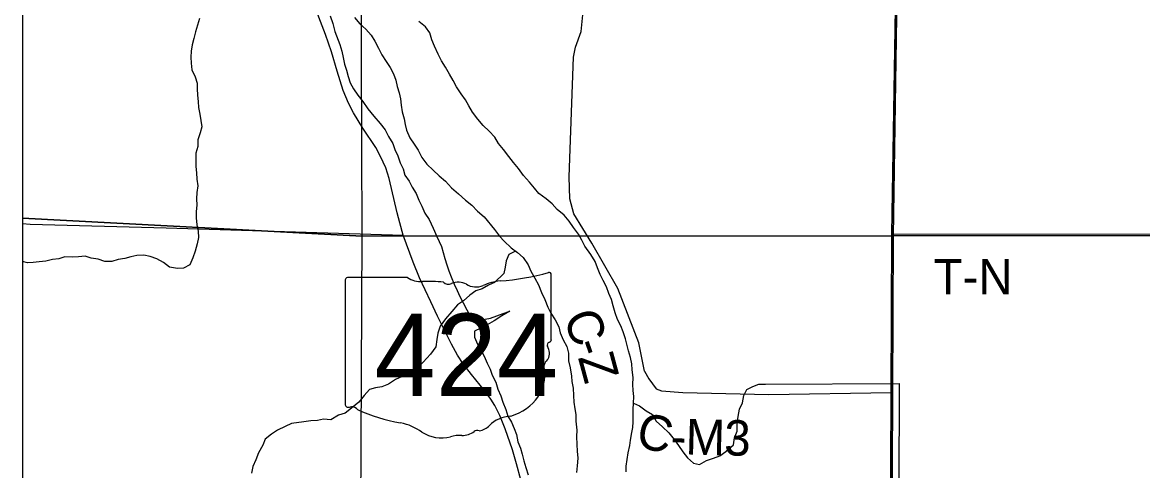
# Model space of a CAD drawing. Extents: x -6.2 to 37.4, y 0.2 to 22.2.
# Drawn here: x 1.681 to 2.577, y 15.692 to 16.05 of the extents above; entities that cross this region are included whole.
import ezdxf

# ---------------------------------------------------------------- set-up
doc = ezdxf.new("R2010")
doc.units = 0
for name, color, linetype in [('GM_X_County_Road', 7, 'Continuous'), ('GM_X_County_Road_Text', 7, 'Continuous'), ('GM_X_Major_River', 7, 'Continuous'), ('GM_X_Minor_River', 7, 'Continuous'), ('GM_X_Rail_Line', 7, 'Continuous'), ('GM_X_Section', 7, 'Continuous'), ('GM_X_State_Location', 7, 'Continuous'), ('GM_X_State_Shield', 7, 'Continuous'), ('GM_X_Township_Road', 7, 'Continuous'), ('GM_X_Township_Road_Text', 7, 'Continuous'), ('GM_X_US_Shield', 7, 'Continuous'), ('SH_Cut_Line', 7, 'Continuous'), ('SH_Data', 7, 'Continuous')]:
    doc.layers.add(name, color=color, linetype=linetype)

msp = doc.modelspace()

# ---------------------------------------------------------------- linework, layer by layer
at = {"layer": 'GM_X_County_Road'}
for points in [[(2.17886, 15.77135), (2.17423, 15.79416), (2.15735, 15.83754), (2.13664, 15.8739), (2.12213, 15.89714), (2.11897, 15.90931), (2.11849, 15.92697), (2.12203, 16.02247), (2.12359, 16.03044), (2.12822, 16.04296), (2.13103, 16.07276), (2.1317, 16.09117), (2.13443, 16.10446), (2.14488, 16.13992), (2.16169, 16.19805), (2.20351, 16.34266), (2.20755, 16.35308), (2.21368, 16.36217), (2.32755, 16.53511), (2.34687, 16.56576), (2.35511, 16.57606), (2.36464, 16.58624), (2.37224, 16.59399), (2.38743, 16.6095)], [(2.3744, 15.3797), (2.37573, 15.63221), (2.37619, 15.75431), (2.37666, 15.88116), (2.38391, 16.32379), (2.3895, 16.61161)], [(2.07985, 15.68454), (2.07645, 15.69747), (2.07312, 15.70847), (2.06716, 15.7254), (2.06302, 15.73606), (2.05889, 15.74394), (2.05591, 15.74906), (2.05083, 15.75596), (2.04021, 15.76886), (2.03362, 15.77727), (2.02899, 15.78432), (2.0243, 15.79294), (2.01897, 15.80363), (2.01322, 15.81555), (2.00779, 15.8268), (1.99868, 15.84597), (1.99355, 15.85851), (1.98575, 15.88021), (1.9829, 15.89009), (1.98084, 15.89805), (1.97446, 15.92542), (1.97165, 15.93408), (1.96762, 15.94322), (1.96366, 15.95037), (1.95343, 15.9658), (1.94589, 15.97796), (1.94176, 15.98563), (1.93769, 15.99594), (1.93282, 16.01129), (1.92833, 16.02671), (1.92346, 16.04076), (1.91333, 16.06715)], [(2.17886, 15.77135), (2.18225, 15.76545), (2.1881, 15.75745), (2.19227, 15.75572), (2.20955, 15.75431), (2.27832, 15.75267), (2.37619, 15.75431)]]:
    msp.add_lwpolyline(points, dxfattribs=at)
at = {"layer": 'GM_X_Major_River'}
for points in [[(1.94657, 16.05425), (1.95084, 16.04906), (1.9557, 16.045), (1.96004, 16.04005), (1.96293, 16.0354), (1.96587, 16.02985), (1.96866, 16.0245), (1.97194, 16.01913), (1.97527, 16.01414), (1.97799, 16.00925), (1.97965, 16.00402), (1.98089, 15.99906), (1.98251, 15.9941), (1.98356, 15.98915), (1.98405, 15.98421), (1.9849, 15.97869), (1.98633, 15.97335), (1.9872, 15.9686), (1.98837, 15.96406), (1.991, 15.9581), (1.99432, 15.95292), (1.99765, 15.94813), (2.00058, 15.9422), (2.00448, 15.93701), (2.00951, 15.93219), (2.01455, 15.92756), (2.01941, 15.92331), (2.02443, 15.91792), (2.02985, 15.91328), (2.03545, 15.90826), (2.04069, 15.9042), (2.04516, 15.89939), (2.05058, 15.89475), (2.05875, 15.88475), (2.06264, 15.87938), (2.06636, 15.87527), (2.07215, 15.87013), (2.07706, 15.86629), (2.08166, 15.86223), (2.08556, 15.85645), (2.08794, 15.85128), (2.09107, 15.84592), (2.09382, 15.84038), (2.09637, 15.83445), (2.09912, 15.82872), (2.10148, 15.82261), (2.10386, 15.81783), (2.10729, 15.81259), (2.11012, 15.80691), (2.11136, 15.80215), (2.11373, 15.79661), (2.11668, 15.79125), (2.11791, 15.78592), (2.118, 15.77984), (2.11924, 15.77416), (2.12042, 15.76754), (2.12075, 15.76328), (2.1216, 15.75777), (2.12188, 15.75207), (2.12217, 15.74656), (2.12295, 15.7414), (2.12381, 15.73669), (2.12392, 15.73146), (2.12463, 15.72431), (2.12436, 15.71919), (2.12463, 15.71274), (2.12491, 15.70742), (2.12539, 15.7019), (2.12491, 15.69584), (2.12443, 15.69034)], [(2.02276, 16.00906), (2.01963, 16.01461), (2.0162, 16.01964), (2.01375, 16.02495), (2.01063, 16.03126), (2.00863, 16.03642), (2.00702, 16.04194), (2.0035, 16.04674), (1.99808, 16.051)], [(2.16406, 15.69088), (2.16414, 15.69562), (2.1648, 15.70074), (2.16584, 15.70604), (2.16696, 15.71208), (2.16749, 15.71636), (2.16856, 15.72245), (2.16941, 15.72652), (2.16967, 15.73103), (2.16976, 15.73597), (2.16965, 15.74091), (2.16993, 15.74584), (2.17021, 15.75115), (2.16972, 15.75609), (2.16942, 15.76084), (2.16971, 15.76634), (2.16887, 15.77262), (2.16876, 15.77736), (2.1677, 15.78231), (2.16609, 15.78765), (2.1636, 15.79718), (2.16161, 15.80291), (2.1598, 15.80768), (2.15723, 15.81284), (2.15542, 15.81799), (2.15381, 15.82371), (2.15238, 15.82867), (2.15038, 15.83364), (2.14839, 15.83898), (2.14582, 15.84395), (2.14343, 15.84874), (2.14125, 15.85408), (2.13944, 15.85901), (2.13594, 15.86479), (2.13104, 15.87146), (2.12874, 15.8761), (2.12598, 15.88108), (2.12208, 15.88626), (2.11857, 15.89144), (2.11461, 15.89631), (2.10894, 15.9008), (2.10497, 15.90512), (2.10011, 15.90937), (2.09429, 15.91361), (2.09078, 15.91787), (2.08688, 15.92267), (2.08185, 15.92787), (2.07796, 15.93344), (2.07388, 15.93843), (2.07017, 15.94323), (2.0659, 15.94861), (2.06181, 15.95361), (2.05887, 15.95859), (2.05459, 15.9634), (2.04974, 15.96784), (2.04527, 15.97303), (2.04101, 15.9786), (2.03825, 15.98358), (2.03549, 15.98836), (2.03216, 15.99316), (2.02828, 15.99891), (2.02552, 16.00389), (2.02276, 16.00906)]]:
    msp.add_lwpolyline(points, dxfattribs=at)
at = {"layer": 'GM_X_Minor_River'}
for points in [[(1.82259, 16.05347), (1.81937, 16.04289), (1.81814, 16.0374), (1.81673, 16.0323), (1.81607, 16.02737), (1.8158, 16.02244), (1.81591, 16.01769), (1.81639, 16.01237), (1.81914, 16.00683), (1.82076, 16.00186), (1.82068, 15.99712), (1.82097, 15.99218), (1.82145, 15.98705), (1.82175, 15.9823), (1.8228, 15.97697), (1.82366, 15.97183), (1.82452, 15.96688), (1.82311, 15.96197), (1.82131, 15.9563), (1.82122, 15.95099), (1.8198, 15.9457), (1.8197, 15.93981), (1.81981, 15.93507), (1.82029, 15.92993), (1.8204, 15.925), (1.82125, 15.91967), (1.8206, 15.91436), (1.82032, 15.90924), (1.82061, 15.90411), (1.81996, 15.89919), (1.82006, 15.89406), (1.82054, 15.88855), (1.82159, 15.88341), (1.82169, 15.87828), (1.82085, 15.87336), (1.81904, 15.86731), (1.81724, 15.86203), (1.81487, 15.85656), (1.80971, 15.85379), (1.80497, 15.85367), (1.79854, 15.85453), (1.79367, 15.8584), (1.78842, 15.86132), (1.78314, 15.86311), (1.77804, 15.86414), (1.77235, 15.86384), (1.76759, 15.86278), (1.76283, 15.86152), (1.75751, 15.86065), (1.75255, 15.85902), (1.74686, 15.85911), (1.7414, 15.8609), (1.73591, 15.86174), (1.73102, 15.86352), (1.7257, 15.86284), (1.72058, 15.86273), (1.7147, 15.86282), (1.70993, 15.86118), (1.705, 15.86069), (1.69967, 15.85944), (1.69435, 15.85876), (1.6896, 15.85827), (1.68486, 15.85796), (1.68086, 15.85906)], [(1.92726, 16.05549), (1.92924, 16.04938), (1.93103, 16.04309), (1.93502, 16.03259), (1.93644, 16.02726), (1.93769, 16.0223), (1.93873, 16.01697), (1.94035, 16.01201), (1.9416, 16.00706), (1.94322, 16.0021), (1.94579, 15.99713), (1.94931, 15.99214), (1.95339, 15.98714), (1.95727, 15.9812), (1.9621, 15.97543), (1.96712, 15.96947), (1.9712, 15.96447), (1.97395, 15.95912), (1.97746, 15.95337), (1.97908, 15.9486), (1.98127, 15.94363), (1.98326, 15.93791), (1.98564, 15.93312), (1.98707, 15.92817), (1.9904, 15.92337), (1.99279, 15.91859), (1.99593, 15.91361), (1.99811, 15.90807), (2.00068, 15.90329), (2.00305, 15.89774), (2.00638, 15.89276), (2.00967, 15.88588), (2.01259, 15.879), (2.01624, 15.87116), (2.01911, 15.86163), (2.02054, 15.85648), (2.02217, 15.85171), (2.02398, 15.84694), (2.02635, 15.84102), (2.02891, 15.83585), (2.0311, 15.83108), (2.03367, 15.8261), (2.03661, 15.82055), (2.03937, 15.81539), (2.04709, 15.81223), (2.05545, 15.81381), (2.06061, 15.81582), (2.06556, 15.81746), (2.0709, 15.81946), (2.06458, 15.81557), (2.05845, 15.81168), (2.0529, 15.80854), (2.04773, 15.80577), (2.04276, 15.80338), (2.04268, 15.79863), (2.04505, 15.79309), (2.048, 15.78811), (2.05057, 15.78333), (2.05294, 15.77779), (2.05514, 15.77301), (2.05676, 15.76824), (2.0597, 15.76269), (2.06131, 15.75697), (2.06387, 15.75162), (2.06549, 15.74666), (2.06786, 15.74074), (2.06929, 15.73559), (2.07243, 15.7308), (2.07442, 15.72564), (2.07624, 15.72087), (2.07746, 15.71497), (2.07965, 15.70981), (2.0809, 15.70504), (2.08213, 15.69971), (2.08394, 15.69437), (2.08573, 15.68846)], [(2.07548, 15.86753), (2.07016, 15.86465), (2.06817, 15.85956), (2.06733, 15.85463), (2.0663, 15.84952), (2.05878, 15.84243), (2.05401, 15.84022), (2.04884, 15.83726), (2.04388, 15.83563), (2.03909, 15.83228), (2.03389, 15.82781), (2.0291, 15.82446), (2.02446, 15.81922), (2.01962, 15.81341), (2.01516, 15.8074), (2.01336, 15.80173), (2.0127, 15.79681), (2.01184, 15.79094), (2.00757, 15.78493), (2.00159, 15.77856), (1.99522, 15.77202), (1.98988, 15.76982), (1.9849, 15.76724), (1.97955, 15.76485), (1.97399, 15.76114), (1.96865, 15.75894), (1.96352, 15.75807), (1.95857, 15.75682), (1.9545, 15.75194), (1.95024, 15.74669), (1.94428, 15.74185), (1.93929, 15.73775), (1.93376, 15.73631), (1.92763, 15.73242), (1.92196, 15.73308), (1.91701, 15.73201), (1.9117, 15.73171), (1.906, 15.73104), (1.8963, 15.72948), (1.89115, 15.72709), (1.88503, 15.72433), (1.88024, 15.72118), (1.87524, 15.71708), (1.87326, 15.71218), (1.86994, 15.70615), (1.86776, 15.70068), (1.86539, 15.69521), (1.86416, 15.68992)], [(2.16993, 15.74584), (2.17482, 15.74386), (2.18006, 15.7398), (2.18512, 15.73668), (2.18826, 15.73151), (2.1933, 15.72707), (2.19834, 15.72225), (2.20242, 15.71687), (2.20613, 15.71207), (2.20945, 15.70708), (2.21316, 15.70209), (2.21801, 15.69784), (2.22293, 15.69682), (2.22848, 15.70015), (2.23401, 15.70197), (2.23897, 15.70379), (2.24395, 15.70713), (2.24992, 15.71255), (2.25096, 15.71804), (2.25295, 15.72351), (2.25305, 15.72901), (2.25372, 15.73527), (2.25495, 15.74094), (2.25713, 15.74622), (2.25836, 15.7519), (2.26072, 15.7568), (2.2655, 15.7592), (2.27027, 15.76102), (2.2741, 15.76106), (2.27558, 15.76113)], [(2.27558, 15.76113), (2.38269, 15.7616), (2.38148, 15.42375)]]:
    msp.add_lwpolyline(points, dxfattribs=at)
at = {"layer": 'GM_X_Rail_Line'}
msp.add_lwpolyline([(1.68086, 18.39138), (1.68086, 15.3872)], dxfattribs=at)
at = {"layer": 'GM_X_Section'}
for points in [[(2.38563, 16.38809), (2.37779, 15.87968), (1.95281, 15.87951), (1.95104, 16.39075)], [(2.38563, 16.38809), (2.89289, 16.38152), (2.88369, 15.88338), (2.88344, 15.87997), (2.37779, 15.87968)], [(2.37779, 15.87968), (2.37562, 15.38046), (1.95052, 15.38351), (1.95281, 15.87951)], [(2.88344, 15.87997), (2.8728, 15.37579), (2.37903, 15.38039), (2.37562, 15.38046), (2.37779, 15.87968)]]:
    msp.add_lwpolyline(points, close=True, dxfattribs=at)
at = {"layer": 'GM_X_State_Shield'}
for p, q in [((1.93933, 15.84451), (1.93933, 15.74445)), ((1.98921, 15.84624), (1.94095, 15.84624)), ((2.10412, 15.79637), (2.10412, 15.84872)), ((2.1041, 15.79639), (2.10412, 15.79637))]:
    msp.add_line(p, q, dxfattribs=at)
for centre, major_axis, start_param, end_param in [((1.94122, 15.84473), (0.00191, 0), 1.712693, 3.28349), ((2.0007, 15.85785), (0.01852, 0), 4.042523, 4.731795), ((2.00684, 15.79006), (0.06648, 0), 1.404758, 1.657858), ((2.06771, 15.81568), (0.03516, 0), 1.699011, 2.107814), ((2.04542, 15.98265), (0.17476, 0), 4.814394, 5.042369), ((2.10229, 15.84893), (0.00183, 0), 6.141152, 7.989035), ((2.02194, 15.84525), (0.00534, 0), 3.836095, 5.185415), ((2.02978, 15.83368), (0.01111, 0), 0.950623, 2.079405), ((2.04411, 15.84954), (0.01336, 0), 4.081561, 5.145723), ((2.1037, 15.79253), (0.00284, 0), 1.883978, 3.671073), ((2.08563, 15.78591), (0.01704, 0), 5.934695, 6.695948), ((2.10216, 15.79617), (0.00196, 0), 5.05454, 6.418171), ((2.11069, 15.77447), (0.0124, 0), 2.387724, 3.262537), ((2.05521, 15.76781), (0.04371, 0), 5.101752, 6.440018), ((1.94123, 15.74424), (0.00193, 0), 3.00124, 4.508301), ((1.94153, 15.75447), (0.0147, 0), 4.665946, 4.897461), ((1.94453, 15.73868), (0.0053, 0), 0.519207, 1.627899), ((2.01145, 15.82858), (0.1262, 0), 4.195997, 4.488961), ((1.97382, 15.6995), (0.03949, 0), 0.823519, 1.323587), ((2.04331, 15.73476), (0.01412, 0), 4.937069, 5.64225), ((2.07364, 15.71636), (0.02394, 0), 1.647645, 2.488434), ((2.01653, 15.73819), (0.02506, 0), 4.026481, 4.996735), ((2.031, 15.70359), (0.02059, 0), 1.495662, 1.94098), ((2.03283, 15.73069), (0.01335, 0), 4.691044, 5.507374), ((2.04491, 15.721), (0.00376, 0), 1.147584, 2.315152)]:
    msp.add_ellipse(centre, major_axis=major_axis, ratio=0.8, start_param=start_param, end_param=end_param, dxfattribs=at)
at = {"layer": 'GM_X_Township_Road'}
msp.add_line((2.37666, 15.88116), (2.76168, 15.88091), dxfattribs=at)
msp.add_lwpolyline([(1.68086, 15.88954), (1.68718, 15.88906), (1.79603, 15.88609), (1.98575, 15.88021)], dxfattribs=at)
at = {"layer": 'GM_X_US_Shield'}
for points in [[(1.68086, 16.39384), (1.68086, 15.89387), (1.95281, 15.87951), (1.95104, 16.39075)], [(1.68086, 15.89387), (1.68086, 15.38487), (1.86735, 15.38393), (1.95052, 15.38351), (1.95281, 15.87951)]]:
    msp.add_lwpolyline(points, close=True, dxfattribs=at)
at = {"layer": 'SH_Cut_Line'}
msp.add_lwpolyline([(1.68086, 20.39726), (1.68086, 14.30742)], dxfattribs=at)
at = {"layer": 'SH_Data'}
msp.add_line((1.68086, 21.10742), (1.68086, 14.30742), dxfattribs=at)

# ---------------------------------------------------------------- texts
at = {"layer": 'GM_X_County_Road_Text'}
for s, rotation, p in [('C', 291.13391, (2.11338, 15.81451)), ('-', 289.31621, (2.12171, 15.79297)), ('Z', 285.11831, (2.12541, 15.78248)), ('C', 347.24175, (2.17091, 15.71128)), ('M', 358.47424, (2.21136, 15.70493)), ('3', 358.8246, (2.24237, 15.70411)), ('-', 357.82032, (2.19934, 15.70539))]:
    msp.add_text(s, height=0.02841, rotation=rotation, dxfattribs=at).set_placement(p)
at = {"layer": 'GM_X_State_Location'}
msp.add_text('424', height=0.0000947, rotation=0.00001, dxfattribs=at).set_placement((1.98644, 15.78094))
for s in ['s', 'r']:
    msp.add_text(s, height=0.0000947, dxfattribs=at).set_placement((2.01987, 15.78783))
at = {"layer": 'GM_X_State_Shield'}
msp.add_text('424', height=0.065918, dxfattribs=at).set_placement((1.96259, 15.75151))
at = {"layer": 'GM_X_Township_Road_Text'}
msp.add_text('T-N', height=0.028409, rotation=0.00001, dxfattribs=at).set_placement((2.41019, 15.8328))

doc.saveas('drawing.dxf')
